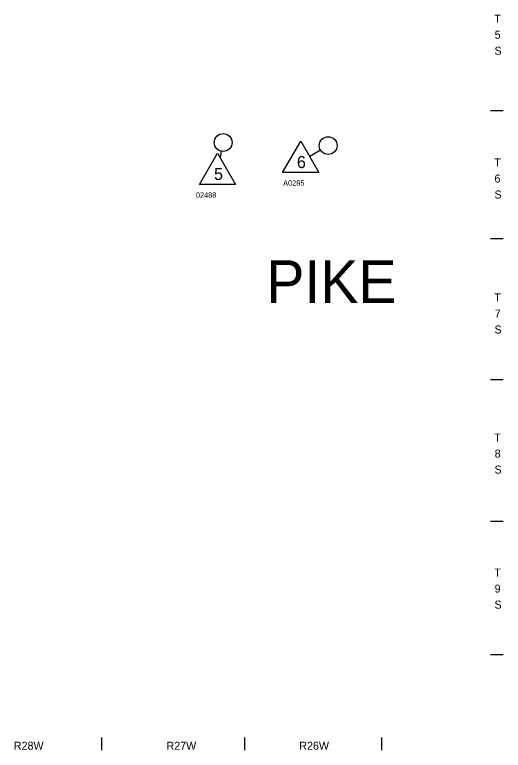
# Model space of a CAD drawing. Extents: x -17742 to 32032, y -17264 to 5867.
# Drawn here: x -10959 to -7299, y -2283 to 3229 of the extents above; entities that cross this region are included whole.
import ezdxf

# ---------------------------------------------------------------- set-up
doc = ezdxf.new("R2010")
doc.units = 0
for name, color, linetype in [('2', 7, 'Continuous'), ('Default', 7, 'Continuous'), ('R_Annotation', 7, 'Continuous'), ('R_No Plot', 7, 'Continuous')]:
    doc.layers.add(name, color=color, linetype=linetype)

msp = doc.modelspace()

# ---------------------------------------------------------------- linework, layer by layer
at = {"layer": 'Default'}
for p, q in [((-7299, 2509.5), (-7394, 2509.5)), ((-7299, 1549.7), (-7394, 1549.7)), ((-7299, 493), (-7394, 493)), ((-7299, -569), (-7394, -569)), ((-7299, -1568.1), (-7394, -1568.1)), ((-10310, -2187.7), (-10310, -2282.7)), ((-9239.1, -2187.7), (-9239.1, -2282.7)), ((-8212.3, -2187.7), (-8212.3, -2282.7))]:
    msp.add_line(p, q, dxfattribs=at)
at = {"layer": 'R_Annotation'}
for p, q in [((-9413.6, 2206.9), (-9421, 2159.9)), ((-8668.4, 2214.3), (-8749.3, 2166.1))]:
    msp.add_line(p, q, dxfattribs=at)
for points in [[(-8817, 2280.8), (-8682, 2047), (-8952, 2047)], [(-9440.4, 2191.6), (-9305.4, 1957.8), (-9575.4, 1957.8)]]:
    msp.add_lwpolyline(points, close=True, dxfattribs=at)
for centre in [(-9398, 2271.7), (-8611.1, 2248.4)]:
    msp.add_circle(centre, 66.7, dxfattribs=at)

# ---------------------------------------------------------------- texts
at = {"layer": '2'}
for s, height, p in [('T', 60, (-7366.1, 3169)), ('5', 60, (-7363.5, 3049)), ('S', 60, (-7365, 2929)), ('T', 60, (-7366.1, 2091.8)), ('6', 60, (-7365.2, 1971.8)), ('S', 60, (-7365, 1851.8)), ('PIKE', 320, (-9073.7, 1069.3)), ('T', 60, (-7366.1, 1080.1)), ('7', 60, (-7363.5, 960.1)), ('S', 60, (-7365, 840.1)), ('T', 60, (-7366.1, 30.6)), ('8', 60, (-7363.5, -89.4)), ('S', 60, (-7365, -209.4)), ('T', 60, (-7366.1, -981.1)), ('9', 60, (-7363.8, -1101.1)), ('S', 60, (-7365, -1221.1)), ('R28W', 60, (-10966.1, -2278.5)), ('R27W', 60, (-9822.2, -2278.5)), ('R26W', 60, (-8827.6, -2278.5))]:
    msp.add_text(s, height=height, dxfattribs=at).set_placement(p)
at = {"layer": 'R_Annotation'}
for s, p in [('6', (-8845, 2080)), ('5', (-9465.9, 1990.7))]:
    msp.add_text(s, height=90, dxfattribs=at).set_placement(p)
at = {"layer": 'R_No Plot'}
for s, p in [('A0285', (-8948.3, 1947.5)), ('02488', (-9602.3, 1857.4))]:
    msp.add_text(s, height=40, dxfattribs=at).set_placement(p)

doc.saveas('drawing.dxf')
